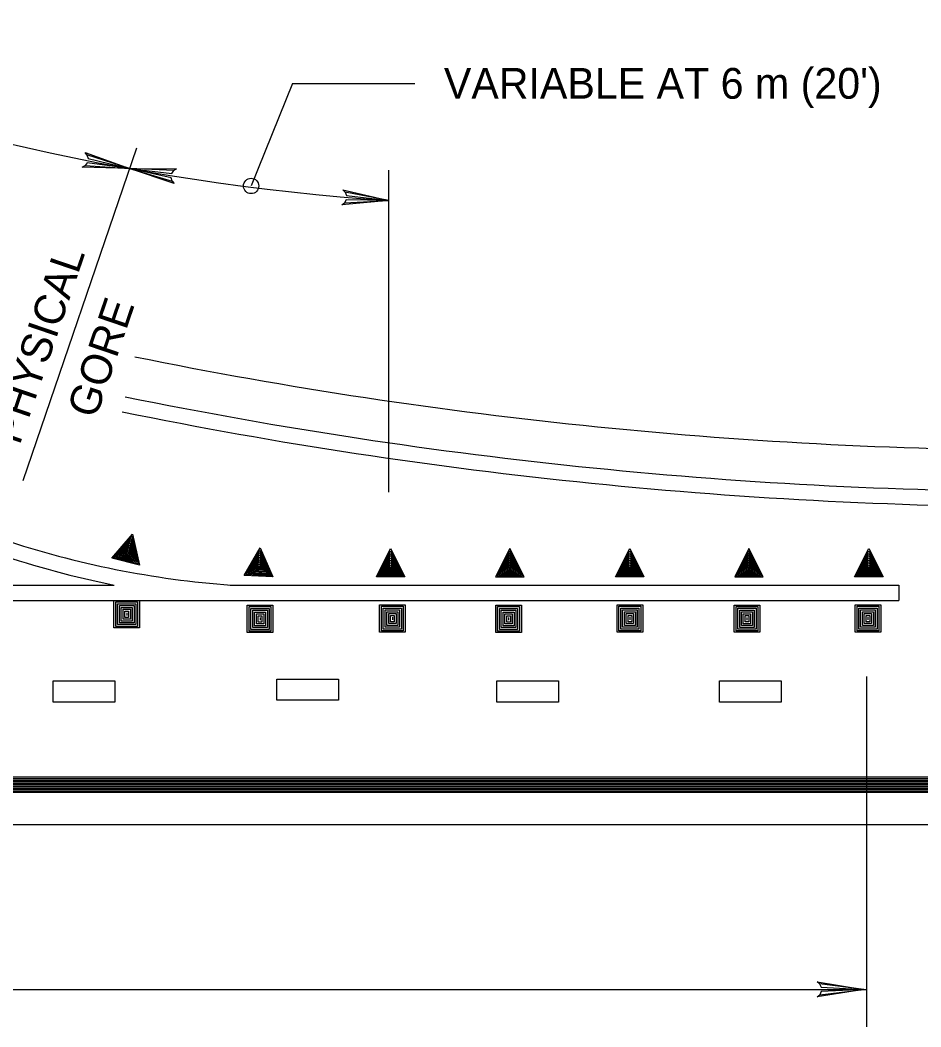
# Model space of a CAD drawing. Extents: x 639362 to 641108, y 298458 to 299646.
# Drawn here: x 639651.2 to 639739, y 299460.6 to 299558.8 of the extents above; entities that cross this region are included whole.
import ezdxf

# ---------------------------------------------------------------- set-up
doc = ezdxf.new("R2010")
doc.units = 0
doc.layers.add('2', color=7, linetype='Continuous')

msp = doc.modelspace()

# ---------------------------------------------------------------- linework, layer by layer
at = {"layer": '2'}
for p, q in [((639677.719, 299552.596), (639673.696, 299542.604)), ((639677.719, 299552.596), (639689.642, 299552.596)), ((639662.521, 299546.295), (639651.455, 299513.868)), ((639687.13, 299512.737), (639687.13, 299544.13)), ((639660.11, 299506.314), (639662.124, 299508.671)), ((639660.286, 299506.37), (639662.073, 299508.458)), ((639662.073, 299508.458), (639662.67, 299505.777)), ((639662.124, 299508.671), (639662.799, 299505.642)), ((639660.47, 299506.432), (639662.016, 299508.239)), ((639660.646, 299506.486), (639661.966, 299508.025)), ((639660.826, 299506.539), (639661.912, 299507.812)), ((639661.003, 299506.605), (639661.856, 299507.6)), ((639661.856, 299507.6), (639662.144, 299506.314)), ((639661.912, 299507.812), (639662.275, 299506.182)), ((639661.966, 299508.025), (639662.407, 299506.046)), ((639662.016, 299508.239), (639662.536, 299505.913)), ((639662.536, 299505.913), (639660.47, 299506.432)), ((639662.407, 299506.046), (639660.646, 299506.486)), ((639662.275, 299506.182), (639660.826, 299506.539)), ((639662.144, 299506.314), (639661.003, 299506.605)), ((639661.183, 299506.658), (639661.809, 299507.384)), ((639662.015, 299506.452), (639661.183, 299506.658)), ((639661.364, 299506.713), (639661.748, 299507.167)), ((639661.883, 299506.589), (639661.364, 299506.713)), ((639661.535, 299506.777), (639661.696, 299506.956)), ((639661.748, 299506.72), (639661.535, 299506.777)), ((639661.696, 299506.956), (639661.748, 299506.72)), ((639661.748, 299507.167), (639661.883, 299506.589)), ((639661.809, 299507.384), (639662.015, 299506.452)), ((639673.034, 299504.633), (639674.563, 299507.334)), ((639673.197, 299504.725), (639674.551, 299507.111)), ((639673.362, 299504.815), (639674.536, 299506.889)), ((639673.527, 299504.905), (639674.529, 299506.67)), ((639673.693, 299504.999), (639674.519, 299506.448)), ((639674.519, 299506.448), (639675.182, 299504.922)), ((639674.529, 299506.67), (639675.342, 299504.805)), ((639674.536, 299506.889), (639675.491, 299504.7)), ((639674.551, 299507.111), (639675.648, 299504.596)), ((639674.563, 299507.334), (639675.803, 299504.489)), ((639685.908, 299504.489), (639687.293, 299507.262)), ((639686.068, 299504.584), (639687.297, 299507.042)), ((639686.229, 299504.685), (639687.295, 299506.819)), ((639686.389, 299504.784), (639687.297, 299506.599)), ((639687.293, 299507.262), (639688.683, 299504.487)), ((639687.295, 299506.819), (639688.363, 299504.686)), ((639687.297, 299507.042), (639688.523, 299504.584)), ((639687.297, 299506.599), (639688.203, 299504.785)), ((639698.914, 299507.262), (639697.525, 299504.487)), ((639698.91, 299507.042), (639697.685, 299504.584)), ((639698.913, 299506.819), (639697.844, 299504.686)), ((639698.91, 299506.599), (639698.004, 299504.785)), ((639700.14, 299504.584), (639698.91, 299507.042)), ((639699.819, 299504.784), (639698.91, 299506.599)), ((639699.979, 299504.685), (639698.913, 299506.819)), ((639700.3, 299504.489), (639698.914, 299507.262)), ((639709.22, 299504.489), (639710.605, 299507.262)), ((639709.379, 299504.584), (639710.609, 299507.042)), ((639709.541, 299504.685), (639710.606, 299506.819)), ((639709.7, 299504.784), (639710.609, 299506.599)), ((639710.605, 299507.262), (639711.994, 299504.487)), ((639710.606, 299506.819), (639711.675, 299504.686)), ((639710.609, 299507.042), (639711.835, 299504.584)), ((639710.609, 299506.599), (639711.515, 299504.785)), ((639722.226, 299507.262), (639720.836, 299504.487)), ((639722.222, 299507.042), (639720.996, 299504.584)), ((639722.224, 299506.819), (639721.156, 299504.686)), ((639722.222, 299506.599), (639721.316, 299504.785)), ((639723.451, 299504.584), (639722.222, 299507.042)), ((639723.13, 299504.784), (639722.222, 299506.599)), ((639723.29, 299504.685), (639722.224, 299506.819)), ((639723.611, 299504.489), (639722.226, 299507.262)), ((639732.531, 299504.489), (639733.917, 299507.262)), ((639732.691, 299504.584), (639733.921, 299507.042)), ((639732.852, 299504.685), (639733.918, 299506.819)), ((639733.012, 299504.784), (639733.921, 299506.599)), ((639733.917, 299507.262), (639735.306, 299504.487)), ((639733.918, 299506.819), (639734.987, 299504.686)), ((639733.921, 299507.042), (639735.146, 299504.584)), ((639733.921, 299506.599), (639734.827, 299504.785)), ((639662.799, 299505.642), (639660.11, 299506.314)), ((639662.67, 299505.777), (639660.286, 299506.37)), ((639673.858, 299505.09), (639674.502, 299506.231)), ((639674.021, 299505.177), (639674.494, 299506.01)), ((639674.18, 299505.268), (639674.482, 299505.789)), ((639674.35, 299505.358), (639674.468, 299505.564)), ((639674.468, 299505.564), (639674.564, 299505.351)), ((639674.482, 299505.789), (639674.719, 299505.241)), ((639674.494, 299506.01), (639674.876, 299505.136)), ((639674.502, 299506.231), (639675.032, 299505.025)), ((639686.549, 299504.884), (639687.3, 299506.375)), ((639686.708, 299504.983), (639687.293, 299506.157)), ((639686.868, 299505.081), (639687.297, 299505.934)), ((639687.025, 299505.184), (639687.295, 299505.712)), ((639687.184, 299505.279), (639687.295, 299505.492)), ((639687.293, 299506.157), (639687.884, 299504.982)), ((639687.295, 299505.712), (639687.563, 299505.18)), ((639687.295, 299505.492), (639687.402, 299505.279)), ((639687.297, 299505.934), (639687.723, 299505.08)), ((639687.3, 299506.375), (639688.042, 299504.882)), ((639698.908, 299506.375), (639698.165, 299504.882)), ((639698.914, 299506.157), (639698.324, 299504.982)), ((639698.91, 299505.934), (639698.485, 299505.08)), ((639698.913, 299505.712), (639698.645, 299505.18)), ((639698.913, 299505.492), (639698.806, 299505.279)), ((639699.659, 299504.884), (639698.908, 299506.375)), ((639699.339, 299505.081), (639698.91, 299505.934)), ((639699.182, 299505.184), (639698.913, 299505.712)), ((639699.024, 299505.279), (639698.913, 299505.492)), ((639699.499, 299504.983), (639698.914, 299506.157)), ((639709.86, 299504.884), (639710.612, 299506.375)), ((639710.02, 299504.983), (639710.605, 299506.157)), ((639710.18, 299505.081), (639710.609, 299505.934)), ((639710.337, 299505.184), (639710.606, 299505.712)), ((639710.495, 299505.279), (639710.606, 299505.492)), ((639710.605, 299506.157), (639711.195, 299504.982)), ((639710.606, 299505.712), (639710.874, 299505.18)), ((639710.606, 299505.492), (639710.713, 299505.279)), ((639710.609, 299505.934), (639711.034, 299505.08)), ((639710.612, 299506.375), (639711.354, 299504.882)), ((639722.219, 299506.375), (639721.477, 299504.882)), ((639722.226, 299506.157), (639721.635, 299504.982)), ((639722.222, 299505.934), (639721.796, 299505.08)), ((639722.224, 299505.712), (639721.956, 299505.18)), ((639722.224, 299505.492), (639722.117, 299505.279)), ((639722.971, 299504.884), (639722.219, 299506.375)), ((639722.651, 299505.081), (639722.222, 299505.934)), ((639722.494, 299505.184), (639722.224, 299505.712)), ((639722.335, 299505.279), (639722.224, 299505.492)), ((639722.811, 299504.983), (639722.226, 299506.157)), ((639733.172, 299504.884), (639733.923, 299506.375)), ((639733.332, 299504.983), (639733.917, 299506.157)), ((639733.492, 299505.081), (639733.921, 299505.934)), ((639733.649, 299505.184), (639733.918, 299505.712)), ((639733.807, 299505.279), (639733.918, 299505.492)), ((639733.917, 299506.157), (639734.507, 299504.982)), ((639733.918, 299505.712), (639734.186, 299505.18)), ((639733.918, 299505.492), (639734.025, 299505.279)), ((639733.921, 299505.934), (639734.346, 299505.08)), ((639733.923, 299506.375), (639734.666, 299504.882)), ((639675.803, 299504.489), (639673.034, 299504.633)), ((639675.648, 299504.596), (639673.197, 299504.725)), ((639675.491, 299504.7), (639673.362, 299504.815)), ((639675.342, 299504.805), (639673.527, 299504.905)), ((639675.182, 299504.922), (639673.693, 299504.999)), ((639675.032, 299505.025), (639673.858, 299505.09)), ((639674.876, 299505.136), (639674.021, 299505.177)), ((639674.719, 299505.241), (639674.18, 299505.268)), ((639674.564, 299505.351), (639674.35, 299505.358)), ((639688.683, 299504.487), (639685.908, 299504.489)), ((639688.523, 299504.584), (639686.068, 299504.584)), ((639688.363, 299504.686), (639686.229, 299504.685)), ((639688.203, 299504.785), (639686.389, 299504.784)), ((639688.042, 299504.882), (639686.549, 299504.884)), ((639687.884, 299504.982), (639686.708, 299504.983)), ((639687.723, 299505.08), (639686.868, 299505.081)), ((639687.563, 299505.18), (639687.025, 299505.184)), ((639687.402, 299505.279), (639687.184, 299505.279)), ((639697.525, 299504.487), (639700.3, 299504.489)), ((639697.685, 299504.584), (639700.14, 299504.584)), ((639697.844, 299504.686), (639699.979, 299504.685)), ((639698.004, 299504.785), (639699.819, 299504.784)), ((639698.165, 299504.882), (639699.659, 299504.884)), ((639698.324, 299504.982), (639699.499, 299504.983)), ((639698.485, 299505.08), (639699.339, 299505.081)), ((639698.645, 299505.18), (639699.182, 299505.184)), ((639698.806, 299505.279), (639699.024, 299505.279)), ((639711.994, 299504.487), (639709.22, 299504.489)), ((639711.835, 299504.584), (639709.379, 299504.584)), ((639711.675, 299504.686), (639709.541, 299504.685)), ((639711.515, 299504.785), (639709.7, 299504.784)), ((639711.354, 299504.882), (639709.86, 299504.884)), ((639711.195, 299504.982), (639710.02, 299504.983)), ((639711.034, 299505.08), (639710.18, 299505.081)), ((639710.874, 299505.18), (639710.337, 299505.184)), ((639710.713, 299505.279), (639710.495, 299505.279)), ((639720.836, 299504.487), (639723.611, 299504.489)), ((639720.996, 299504.584), (639723.451, 299504.584)), ((639721.156, 299504.686), (639723.29, 299504.685)), ((639721.316, 299504.785), (639723.13, 299504.784)), ((639721.477, 299504.882), (639722.971, 299504.884)), ((639721.635, 299504.982), (639722.811, 299504.983)), ((639721.796, 299505.08), (639722.651, 299505.081)), ((639721.956, 299505.18), (639722.494, 299505.184)), ((639722.117, 299505.279), (639722.335, 299505.279)), ((639735.306, 299504.487), (639732.531, 299504.489)), ((639735.146, 299504.584), (639732.691, 299504.584)), ((639734.987, 299504.686), (639732.852, 299504.685)), ((639734.827, 299504.785), (639733.012, 299504.784)), ((639734.666, 299504.882), (639733.172, 299504.884)), ((639734.507, 299504.982), (639733.332, 299504.983)), ((639734.346, 299505.08), (639733.492, 299505.081)), ((639734.186, 299505.18), (639733.649, 299505.184)), ((639734.025, 299505.279), (639733.807, 299505.279)), ((639511.242, 299503.694), (639660.336, 299503.694)), ((639671.649, 299503.694), (639736.844, 299503.694)), ((639736.844, 299503.694), (639736.844, 299502.194)), ((639511.242, 299502.194), (639736.844, 299502.194)), ((639660.32, 299502.184), (639662.817, 299502.184)), ((639660.32, 299499.532), (639660.32, 299502.184)), ((639660.506, 299502.052), (639662.635, 299502.052)), ((639660.506, 299499.658), (639660.506, 299502.052)), ((639660.684, 299501.875), (639662.458, 299501.875)), ((639660.684, 299499.836), (639660.684, 299501.875)), ((639660.861, 299501.697), (639662.28, 299501.697)), ((639660.861, 299500.013), (639660.861, 299501.697)), ((639662.28, 299501.697), (639662.28, 299500.013)), ((639662.458, 299501.875), (639662.458, 299499.836)), ((639662.635, 299502.052), (639662.635, 299499.658)), ((639662.817, 299502.184), (639662.817, 299499.532)), ((639673.319, 299501.728), (639675.817, 299501.728)), ((639673.319, 299499.076), (639673.319, 299501.728)), ((639673.505, 299501.596), (639675.634, 299501.596)), ((639673.505, 299499.202), (639673.505, 299501.596)), ((639675.634, 299501.596), (639675.634, 299499.202)), ((639675.817, 299501.728), (639675.817, 299499.076)), ((639686.216, 299501.757), (639688.715, 299501.757)), ((639686.216, 299499.105), (639686.216, 299501.757)), ((639686.401, 299501.625), (639688.53, 299501.625)), ((639686.401, 299499.23), (639686.401, 299501.625)), ((639688.53, 299501.625), (639688.53, 299499.23)), ((639688.715, 299501.757), (639688.715, 299499.105)), ((639697.542, 299501.727), (639700.039, 299501.727)), ((639697.542, 299499.075), (639697.542, 299501.727)), ((639697.728, 299501.595), (639699.857, 299501.595)), ((639697.728, 299499.201), (639697.728, 299501.595)), ((639699.857, 299501.595), (639699.857, 299499.201)), ((639700.039, 299501.727), (639700.039, 299499.075)), ((639709.371, 299501.757), (639711.867, 299501.757)), ((639709.371, 299499.105), (639709.371, 299501.757)), ((639709.556, 299501.625), (639711.685, 299501.625)), ((639709.556, 299499.23), (639709.556, 299501.625)), ((639711.685, 299501.625), (639711.685, 299499.23)), ((639711.867, 299501.757), (639711.867, 299499.105)), ((639720.785, 299501.747), (639723.282, 299501.747)), ((639720.785, 299499.095), (639720.785, 299501.747)), ((639720.971, 299501.615), (639723.1, 299501.615)), ((639720.971, 299499.22), (639720.971, 299501.615)), ((639723.1, 299501.615), (639723.1, 299499.22)), ((639723.282, 299501.747), (639723.282, 299499.095)), ((639732.578, 299501.757), (639735.074, 299501.757)), ((639732.578, 299499.105), (639732.578, 299501.757)), ((639732.762, 299501.625), (639734.891, 299501.625)), ((639732.762, 299499.23), (639732.762, 299501.625)), ((639734.891, 299501.625), (639734.891, 299499.23)), ((639735.074, 299501.757), (639735.074, 299499.105)), ((639661.038, 299501.52), (639662.103, 299501.52)), ((639661.038, 299500.191), (639661.038, 299501.52)), ((639661.215, 299500.368), (639661.215, 299501.343)), ((639661.215, 299501.343), (639661.926, 299501.343)), ((639661.393, 299501.167), (639661.749, 299501.167)), ((639661.393, 299500.545), (639661.393, 299501.167)), ((639661.749, 299500.545), (639661.393, 299500.545)), ((639661.57, 299500.987), (639661.57, 299500.722)), ((639661.749, 299501.167), (639661.749, 299500.545)), ((639661.926, 299501.343), (639661.926, 299500.368)), ((639662.103, 299501.52), (639662.103, 299500.191)), ((639673.683, 299501.419), (639675.458, 299501.419)), ((639673.683, 299499.38), (639673.683, 299501.419)), ((639673.86, 299501.241), (639675.28, 299501.241)), ((639673.86, 299499.557), (639673.86, 299501.241)), ((639674.038, 299501.064), (639675.103, 299501.064)), ((639674.038, 299499.735), (639674.038, 299501.064)), ((639674.215, 299499.912), (639674.215, 299500.887)), ((639674.215, 299500.887), (639674.924, 299500.887)), ((639674.394, 299500.711), (639674.748, 299500.711)), ((639674.394, 299500.089), (639674.394, 299500.711)), ((639674.748, 299500.711), (639674.748, 299500.089)), ((639674.924, 299500.887), (639674.924, 299499.912)), ((639675.103, 299501.064), (639675.103, 299499.735)), ((639675.28, 299501.241), (639675.28, 299499.557)), ((639675.458, 299501.419), (639675.458, 299499.38)), ((639686.58, 299501.448), (639688.355, 299501.448)), ((639686.58, 299499.409), (639686.58, 299501.448)), ((639686.759, 299501.269), (639688.177, 299501.269)), ((639686.759, 299499.585), (639686.759, 299501.269)), ((639686.936, 299501.093), (639688, 299501.093)), ((639686.936, 299499.764), (639686.936, 299501.093)), ((639687.113, 299499.941), (639687.113, 299500.916)), ((639687.113, 299500.916), (639687.823, 299500.916)), ((639687.291, 299500.74), (639687.645, 299500.74)), ((639687.291, 299500.118), (639687.291, 299500.74)), ((639687.465, 299500.56), (639687.465, 299500.295)), ((639687.645, 299500.74), (639687.645, 299500.118)), ((639687.823, 299500.916), (639687.823, 299499.941)), ((639688, 299501.093), (639688, 299499.764)), ((639688.177, 299501.269), (639688.177, 299499.585)), ((639688.355, 299501.448), (639688.355, 299499.409)), ((639697.907, 299501.418), (639699.68, 299501.418)), ((639697.907, 299499.379), (639697.907, 299501.418)), ((639698.084, 299501.24), (639699.502, 299501.24)), ((639698.084, 299499.556), (639698.084, 299501.24)), ((639698.261, 299501.063), (639699.325, 299501.063)), ((639698.261, 299499.734), (639698.261, 299501.063)), ((639698.438, 299499.911), (639698.438, 299500.886)), ((639698.438, 299500.886), (639699.148, 299500.886)), ((639698.616, 299500.71), (639698.971, 299500.71)), ((639698.616, 299500.088), (639698.616, 299500.71)), ((639698.971, 299500.71), (639698.971, 299500.088)), ((639699.148, 299500.886), (639699.148, 299499.911)), ((639699.325, 299501.063), (639699.325, 299499.734)), ((639699.502, 299501.24), (639699.502, 299499.556)), ((639699.68, 299501.418), (639699.68, 299499.379)), ((639709.734, 299501.448), (639711.508, 299501.448)), ((639709.734, 299499.409), (639709.734, 299501.448)), ((639709.911, 299501.269), (639711.329, 299501.269)), ((639709.911, 299499.586), (639709.911, 299501.269)), ((639710.088, 299501.093), (639711.153, 299501.093)), ((639710.088, 299499.764), (639710.088, 299501.093)), ((639710.265, 299499.941), (639710.265, 299500.916)), ((639710.265, 299500.916), (639710.976, 299500.916)), ((639710.443, 299500.74), (639710.799, 299500.74)), ((639710.443, 299500.118), (639710.443, 299500.74)), ((639710.62, 299500.56), (639710.62, 299500.295)), ((639710.799, 299500.74), (639710.799, 299500.118)), ((639710.976, 299500.916), (639710.976, 299499.941)), ((639711.153, 299501.093), (639711.153, 299499.764)), ((639711.329, 299501.269), (639711.329, 299499.586)), ((639711.508, 299501.448), (639711.508, 299499.409)), ((639721.149, 299501.438), (639722.923, 299501.438)), ((639721.149, 299499.399), (639721.149, 299501.438)), ((639721.326, 299501.259), (639722.745, 299501.259)), ((639721.326, 299499.575), (639721.326, 299501.259)), ((639721.503, 299501.082), (639722.568, 299501.082)), ((639721.503, 299499.754), (639721.503, 299501.082)), ((639721.68, 299499.931), (639721.68, 299500.905)), ((639721.68, 299500.905), (639722.391, 299500.905)), ((639721.858, 299500.73), (639722.214, 299500.73)), ((639721.858, 299500.108), (639721.858, 299500.73)), ((639722.035, 299500.55), (639722.035, 299500.285)), ((639722.214, 299500.73), (639722.214, 299500.108)), ((639722.391, 299500.905), (639722.391, 299499.931)), ((639722.568, 299501.082), (639722.568, 299499.754)), ((639722.745, 299501.259), (639722.745, 299499.575)), ((639722.923, 299501.438), (639722.923, 299499.399)), ((639732.941, 299501.448), (639734.715, 299501.448)), ((639732.941, 299499.409), (639732.941, 299501.448)), ((639733.118, 299501.269), (639734.536, 299501.269)), ((639733.118, 299499.585), (639733.118, 299501.269)), ((639733.295, 299501.093), (639734.359, 299501.093)), ((639733.295, 299499.764), (639733.295, 299501.093)), ((639733.472, 299499.941), (639733.472, 299500.916)), ((639733.472, 299500.916), (639734.182, 299500.916)), ((639733.65, 299500.74), (639734.005, 299500.74)), ((639733.65, 299500.118), (639733.65, 299500.74)), ((639733.827, 299500.56), (639733.827, 299500.295)), ((639734.005, 299500.74), (639734.005, 299500.118)), ((639734.182, 299500.916), (639734.182, 299499.941)), ((639734.359, 299501.093), (639734.359, 299499.764)), ((639734.536, 299501.269), (639734.536, 299499.585)), ((639734.715, 299501.448), (639734.715, 299499.409)), ((639662.635, 299499.658), (639660.506, 299499.658)), ((639662.458, 299499.836), (639660.684, 299499.836)), ((639662.28, 299500.013), (639660.861, 299500.013)), ((639662.103, 299500.191), (639661.038, 299500.191)), ((639661.926, 299500.368), (639661.215, 299500.368)), ((639675.103, 299499.735), (639674.038, 299499.735)), ((639674.924, 299499.912), (639674.215, 299499.912)), ((639674.748, 299500.089), (639674.394, 299500.089)), ((639674.569, 299500.532), (639674.569, 299500.266)), ((639688.177, 299499.585), (639686.759, 299499.585)), ((639688, 299499.764), (639686.936, 299499.764)), ((639687.823, 299499.941), (639687.113, 299499.941)), ((639687.645, 299500.118), (639687.291, 299500.118)), ((639699.325, 299499.734), (639698.261, 299499.734)), ((639699.148, 299499.911), (639698.438, 299499.911)), ((639698.971, 299500.088), (639698.616, 299500.088)), ((639698.793, 299500.53), (639698.793, 299500.265)), ((639711.329, 299499.586), (639709.911, 299499.586)), ((639711.153, 299499.764), (639710.088, 299499.764)), ((639710.976, 299499.941), (639710.265, 299499.941)), ((639710.799, 299500.118), (639710.443, 299500.118)), ((639722.745, 299499.575), (639721.326, 299499.575)), ((639722.568, 299499.754), (639721.503, 299499.754)), ((639722.391, 299499.931), (639721.68, 299499.931)), ((639722.214, 299500.108), (639721.858, 299500.108)), ((639734.536, 299499.585), (639733.118, 299499.585)), ((639734.359, 299499.764), (639733.295, 299499.764)), ((639734.182, 299499.941), (639733.472, 299499.941)), ((639734.005, 299500.118), (639733.65, 299500.118)), ((639662.817, 299499.532), (639660.32, 299499.532)), ((639675.817, 299499.076), (639673.319, 299499.076)), ((639675.634, 299499.202), (639673.505, 299499.202)), ((639675.458, 299499.38), (639673.683, 299499.38)), ((639675.28, 299499.557), (639673.86, 299499.557)), ((639688.715, 299499.105), (639686.216, 299499.105)), ((639688.53, 299499.23), (639686.401, 299499.23)), ((639688.355, 299499.409), (639686.58, 299499.409)), ((639700.039, 299499.075), (639697.542, 299499.075)), ((639699.857, 299499.201), (639697.728, 299499.201)), ((639699.68, 299499.379), (639697.907, 299499.379)), ((639699.502, 299499.556), (639698.084, 299499.556)), ((639711.867, 299499.105), (639709.371, 299499.105)), ((639711.685, 299499.23), (639709.556, 299499.23)), ((639711.508, 299499.409), (639709.734, 299499.409)), ((639723.282, 299499.095), (639720.785, 299499.095)), ((639723.1, 299499.22), (639720.971, 299499.22)), ((639722.923, 299499.399), (639721.149, 299499.399)), ((639735.074, 299499.105), (639732.578, 299499.105)), ((639734.891, 299499.23), (639732.762, 299499.23)), ((639734.715, 299499.409), (639732.941, 299499.409)), ((639733.677, 299494.768), (639733.677, 299460.625)), ((639654.405, 299492.282), (639654.405, 299494.347)), ((639654.406, 299494.347), (639660.419, 299494.347)), ((639660.419, 299494.347), (639660.419, 299492.282)), ((639676.215, 299492.47), (639676.215, 299494.534)), ((639676.215, 299494.534), (639682.228, 299494.534)), ((639682.228, 299494.534), (639682.228, 299492.47)), ((639697.662, 299492.282), (639697.662, 299494.347)), ((639697.662, 299494.347), (639703.675, 299494.347)), ((639703.675, 299494.347), (639703.675, 299492.282)), ((639719.363, 299492.282), (639719.363, 299494.347)), ((639719.363, 299494.347), (639725.376, 299494.347)), ((639725.376, 299494.347), (639725.376, 299492.282)), ((639660.419, 299492.282), (639654.406, 299492.282)), ((639682.228, 299492.47), (639676.215, 299492.47)), ((639703.675, 299492.282), (639697.662, 299492.282)), ((639725.376, 299492.282), (639719.363, 299492.282)), ((639511.242, 299484.992), (639812.246, 299484.992)), ((639511.242, 299484.842), (639812.246, 299484.842)), ((639511.242, 299484.692), (639812.246, 299484.692)), ((639511.242, 299484.542), (639812.246, 299484.542)), ((639511.242, 299484.392), (639812.246, 299484.392)), ((639511.242, 299484.242), (639812.246, 299484.242)), ((639511.242, 299484.092), (639812.246, 299484.092)), ((639511.242, 299483.942), (639812.246, 299483.942)), ((639511.242, 299483.792), (639812.246, 299483.792)), ((639511.242, 299483.642), (639812.246, 299483.642)), ((639511.242, 299483.492), (639812.246, 299483.492)), ((639511.242, 299480.346), (639812.246, 299480.346)), ((639530.326, 299464.273), (639733.677, 299464.273))]:
    msp.add_line(p, q, dxfattribs=at)
for points in [[(639657.693, 299545.638), (639657.798, 299545.298), (639661.839, 299544.301), (639657.693, 299545.638), (639657.516, 299545.864), (639661.839, 299544.301), (639657.72, 299544.871), (639657.511, 299544.595), (639661.839, 299544.301), (639657.241, 299544.434), (639657.511, 299544.595)], [(639666.013, 299543.065), (639665.901, 299543.398), (639661.84, 299544.303), (639666.013, 299543.065), (639666.198, 299542.841), (639661.84, 299544.303), (639665.972, 299543.83), (639666.173, 299544.108), (639661.84, 299544.303), (639666.434, 299544.274), (639666.173, 299544.108)], [(639682.854, 299542.015), (639682.999, 299541.69), (639687.13, 299541.188), (639682.854, 299542.015), (639682.65, 299542.219), (639687.13, 299541.188), (639682.973, 299541.257), (639682.798, 299540.959), (639687.13, 299541.188), (639682.55, 299540.766), (639682.798, 299540.959)], [(639729.11, 299464.814), (639729.269, 299464.5), (639733.429, 299464.273), (639729.11, 299464.814), (639728.891, 299465.002), (639733.429, 299464.273), (639729.279, 299464.064), (639729.123, 299463.758), (639733.429, 299464.273), (639728.891, 299463.549), (639729.123, 299463.758)]]:
    msp.add_lwpolyline(points, dxfattribs=at)
msp.add_circle((639673.696, 299542.604), 0.75, dxfattribs=at)
for centre, radius, start, end in [((639702.31, 299768.715), 228.032, 247.02471, 266.18309), ((639753.05, 299972.54), 455.7, 258.51992, 270), ((639753.117, 299971.805), 459, 258.47653, 270), ((639753.117, 299971.805), 460.5, 258.47653, 270), ((639678.554, 299595.485), 92.049, 251.57665, 265.76929), ((639679.825, 299599.258), 97.531, 251.55634, 258.47319)]:
    msp.add_arc(centre, radius, start, end, dxfattribs=at)

# ---------------------------------------------------------------- texts
msp.add_text("VARIABLE AT 6 m (20')", height=3, dxfattribs=at).set_placement((639692.49, 299551.109))
for s, p in [('PHYSICAL', (639651.128, 299517.267)), ('GORE', (639658.547, 299519.821))]:
    msp.add_text(s, height=3, rotation=71.15724, dxfattribs=at).set_placement(p)

doc.saveas('drawing.dxf')
